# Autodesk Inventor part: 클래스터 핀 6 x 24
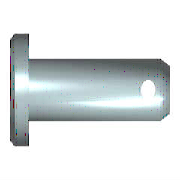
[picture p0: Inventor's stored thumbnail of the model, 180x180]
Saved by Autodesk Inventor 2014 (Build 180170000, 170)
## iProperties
IsCustomPart: 1
Created: 2012-02
Part Number: 클래스터 핀 6 x 24
Material: 강철
Description: 머리가 있는 클레비스 핀
Document SubType Name: Modeling
Standard: ISO 2341
Designer: mduedu
Standard Revision: Second edition 1986-11-01
Standards Organization: ISO
Language: ko-KR
Size Designation: B - 6 x 24
Categories: <MemberInstance><Categories><Category DisplayName="조임쇠" InternalName="e4da775c-781d-43d5-af7c-5136215cf5a6" Mnemonic="FSTN"><Category DisplayName="핀" InternalNa
Density: 7.85 g/cm^3
Appearance: 주황색
Author: mduedu
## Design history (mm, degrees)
sketch "스케치1"
  geometry: L1 (-2, 0)-(-2, 5); L2 (-2, 5)-(0, 5); L3 (0, 5)-(0, 3); L4 (0, 3)-(24, 3); L5 (24, 3)-(24, 0); L6 (-2, 0)-(24, 0); L7 (-4, 0)-(17, 0) reference; L8 (0, -0.98)-(0, 3.08) reference; C1 r 0.8 at (20.8, 0)
  constraints: 12 end point, 3 parallel, 2 collinear, 2 perpendicular, 1 centre point, 1 point on line, 1 vertical
  dimensions: "d0" = 6 diameter of L4 L6 (= NND); "d1" = 10 diameter of L2 L6 (= KOD); "d2" = 2 distance of L1.end L2.end (= KOH); "d3" = 24 distance of L3.end L4.end (= NLG); "d5" = 3.2 distance from line of L5 C1.centre (= DIST); "d6" = 1.6 diameter of C1 (= BOR)
revolve "본체" stored, may be unused: angle "d4" = 90 deg
extrude "구멍" cut sketch "스케치1" stored distance "d7" = 6 (= NND); taper "d8" = 0 deg
workaxis "Work Axis1"
workplane "Work Plane1"
node "작업 평면4"
body "Solid1"
chamfer "모따기1" distance "d9" = 1 (= PHH2); stored, may be unused: angle "d10" = 45 deg (= FAWI2), second distance "d16" = 1 (= PHH2)
chamfer "모따기2" distance "d11" = 2 (= PHH1); stored, may be unused: angle "d12" = 30 deg (= FAWI1), second distance "d17" = 2 (= PHH1)
other parameters: "PHH1" = 2 [user parameter; used in 2 equation terms], "PHH2" = 1 [user parameter; used in 2 equation terms], "KOD" = 10 [user parameter; used in 1 equation term], "KOH" = 2 [user parameter; used in 1 equation term], "NND" = 6 [user parameter; used in 2 equation terms], "FAWI1" = 30 deg [user parameter; used in 1 equation term], "FAWI2" = 45 deg [user parameter; used in 1 equation term], "DIST" = 3.2 [user parameter; used in 1 equation term], "BOR" = 1.6 [user parameter; used in 1 equation term], "NLG" = 24 [user parameter; used in 1 equation term], "d13" = 0, "d14" = 0, "d27" = 0, "d28" = 0, "d29" = 0, "d30" = 0, "d31" = 0, "d32" = -2.75
